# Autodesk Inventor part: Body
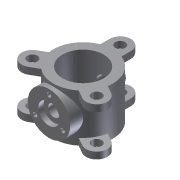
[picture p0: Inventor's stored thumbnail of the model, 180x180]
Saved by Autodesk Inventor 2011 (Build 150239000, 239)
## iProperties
Shininess: 77.0
Length Units: 11269
Angle Units: 11279
Time Units: 11290
Mass Units: 11283
Length Display Precision: 3
Angle Display Precision: 2
Created: 2002-01
Part Number: Body
Document SubType Name: Modeling
Designer: ***
Density: 1 g/cm^3
Density: 0.0
Volumn: 0.0
Area: 0.0
PropertySet Name: Model Information
Control State: 0
Master: False
Checked Out: False
Author: ***
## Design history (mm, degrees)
sketch "Sketch1"
  geometry: C1 r 140 at (0, 0); C2 r 97 at (0, 0)
  constraints: 2 centre point, 1 coincident
  dimensions: "d0" = 280 diameter of C1; "d1" = 194 diameter of C2
extrude "Extrusion1" new body sketch "Sketch1" stored distance "d2" = 225; taper "d3" = 0 deg
sketch "Sketch2"
  geometry: L1 (50, 130.767)-(50, 175); L2 (-50, 175)-(-50, 130.767); C1 r 140 at (0, 0) reference; C2 r 23.5 at (0, 175); A1 r 50 centre (0, 175) between (50, 175) and (-50, 175); A2 r 140 centre (0, 0) between (50, 130.767) and (-50, 130.767)
  constraints: 4 end point, 4 point on circle, 3 centre point, 2 concentric, 2 tangent, 1 coincident, 1 parallel, 1 vertical, 1 vertical alignment
  dimensions: "d4" = 50 radius of A1; "d5" = 175 distance of C1.centre A1.centre; "d6" = 47 diameter of C2
extrude "Extrusion2" join sketch "Sketch2" distance "d7" = 32; taper "d8" = 0 deg
pattern_circular "Circular Pattern1" dims angle "d11" = 360 deg
mirror "Mirror1"
workplane "Work Plane1"
sketch "Sketch3"
  geometry: C1 r 100 at (0.788, 0); C2 r 10 at (0.788, 75); C3 r 10 at (-64.163, -37.5); C4 r 10 at (65.74, -37.5)
  constraints: 4 centre point, 7 other
  dimensions: "d13" = 200 diameter of C1; "d16" = 0 horizontal distance of C1.centre C2.centre; "d17" = 75 distance of C1.centre C2.centre; "d20" = 360 deg dimension on C1.centre C2.centre (derived)
extrude "Extrusion3" join sketch "Sketch3" stored distance "d22" = 32; taper "d23" = 0 deg
workplane "Work Plane2"
sketch "Sketch4"
  geometry: C1 r 37.5 at (0, 0)
  constraints: 1 centre point
  dimensions: "d25" = 75 diameter of C1
extrude "Extrusion4" join sketch "Sketch4" stored distance "d26" = 32; taper "d27" = 0 deg
sketch "Sketch5"
  geometry: C1 r 100 at (0, 0) reference
hole "Hole1" sketch "Sketch5" at (0, 0) diameter "d28" = 56.2; stored, may be unused: countersink angle "d32" = 82 deg, drill point angle "d34" = 0 deg; dims "d29" = 6, "d30" = 100, "d31" = 24, "d33" = 310
sketch "Sketch7"
  geometry: C1 r 50 at (0, 0) reference; 1 further point
  dimensions: "d44" = 75 distance of C1.centre point (0, 75)
hole "Hole2" sketch "Sketch7" at (0, 75) diameter "d45" = 20.3; stored, may be unused: countersink angle "d49" = 82 deg, drill point angle "d51" = 0 deg; dims "d46" = 6, "d47" = 4, "d48" = 2, "d50" = 15
pattern_circular "Circular Pattern2" dims angle "d54" = 360 deg
body "Solid1"
other parameters: "d24" = -325
